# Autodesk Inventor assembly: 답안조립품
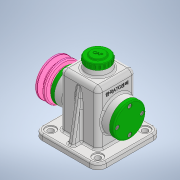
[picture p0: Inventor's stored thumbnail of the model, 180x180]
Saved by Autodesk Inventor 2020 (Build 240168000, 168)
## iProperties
Created: 2021-07
Part Number: 답안조립품
Document SubType Name: Assembly
Designer: Owner
Author: Owner
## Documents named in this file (14)
- C:\Users\Owner\Desktop\710715V1002\답안조립품.iam
- C:\Users\Owner\Desktop\710715V1002\본체.ipt
- C:\Users\Owner\Desktop\710715V1002\V-벨트풀리.ipt
- C:\Users\Owner\Desktop\710715V1002\뒤커버.ipt
- C:\Users\Owner\Desktop\710715V1002\멈춤링 15 x 1.ipt
- C:\Users\Owner\Desktop\710715V1002\베어링 15 x 35 x 11.ipt
- C:\Users\Owner\Desktop\710715V1002\볼트 M4 x 10.ipt
- C:\Users\Owner\Desktop\710715V1002\볼트 M6 x 12.ipt
- C:\Users\Owner\Desktop\710715V1002\상부캡.ipt
- C:\Users\Owner\Desktop\710715V1002\앞커버.ipt
- C:\Users\Owner\Desktop\710715V1002\오일실 15 25 7.ipt
- C:\Users\Owner\Desktop\710715V1002\와셔.ipt
- C:\Users\Owner\Desktop\710715V1002\축.ipt
- C:\Users\Owner\Desktop\710715V1002\키 5 x 5 x 14.ipt
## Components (1 placed, 1 different names)
1. V-벨트풀리:1 — 플러쉬:1
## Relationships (1: Flush 1)
- 플러쉬:1 [Flush]: V-벨트풀리:1
